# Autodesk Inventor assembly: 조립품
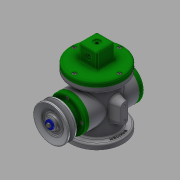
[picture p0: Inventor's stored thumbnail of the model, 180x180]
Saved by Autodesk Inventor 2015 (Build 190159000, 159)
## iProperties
Created: 2018-02
Part Number: 조립품
Document SubType Name: Assembly
Designer: SCD-A03
Author: SCD-A03
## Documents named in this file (18)
- C:\Users\SCD-A03\Desktop\480208V1001\조립품.iam
- C:\Users\SCD-A03\Desktop\480208V1001\본체.ipt
- C:\Users\SCD-A03\Desktop\480208V1001\E-링.ipt
- C:\Users\SCD-A03\Desktop\480208V1001\V-벨트풀리.ipt
- C:\Users\SCD-A03\Desktop\480208V1001\덮개.ipt
- C:\Users\SCD-A03\Desktop\480208V1001\뒤커버.ipt
- C:\Users\SCD-A03\Desktop\480208V1001\링크.ipt
- C:\Users\SCD-A03\Desktop\480208V1001\베어링 17 x 40 x 12.ipt
- C:\Users\SCD-A03\Desktop\480208V1001\볼트 M4 x 8.ipt
- C:\Users\SCD-A03\Desktop\480208V1001\볼트 M4 x 10.ipt
- C:\Users\SCD-A03\Desktop\480208V1001\슬라이더.ipt
- C:\Users\SCD-A03\Desktop\480208V1001\앞커버.ipt
- C:\Users\SCD-A03\Desktop\480208V1001\오일 실 17 30 8.ipt
- C:\Users\SCD-A03\Desktop\480208V1001\와셔 4x16.ipt
- C:\Users\SCD-A03\Desktop\480208V1001\클레비스 핀 6 x 22.ipt
- 클레비스 핀 6 x 22.ipt
- C:\Users\SCD-A03\Desktop\480208V1001\키 4 x 4 x 12.ipt
- C:\Users\SCD-A03\Desktop\480208V1001\편심축.ipt
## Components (2 placed, 2 different names)
1. E-링:1
2. V-벨트풀리:1 — 각도:2
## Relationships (1: Angle 1)
- 각도:2 [Angle]: V-벨트풀리:1
